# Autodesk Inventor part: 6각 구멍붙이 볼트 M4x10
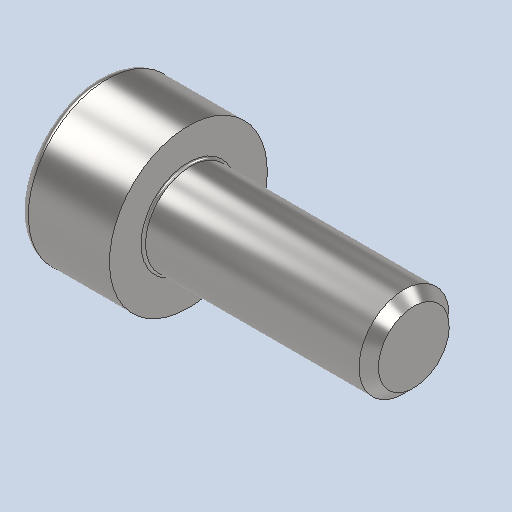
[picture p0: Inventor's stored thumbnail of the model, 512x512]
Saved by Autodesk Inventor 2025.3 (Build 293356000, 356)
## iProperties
Created: 2025-09
Part Number: 6각 구멍붙이 볼트 M4x10
Material: 강철, 연강
Description: 6각머리 태핑 나사
Document SubType Name: Modeling
Designer: PC-15
Density: 7.85 g/cm^3
Appearance: 기본값
Author: jhkim
Sending System: Autodesk Inventor 2026
Preprocessor: ST-DEVELOPER v20.1
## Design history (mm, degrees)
feature "Solid1"
node "솔리드1"
